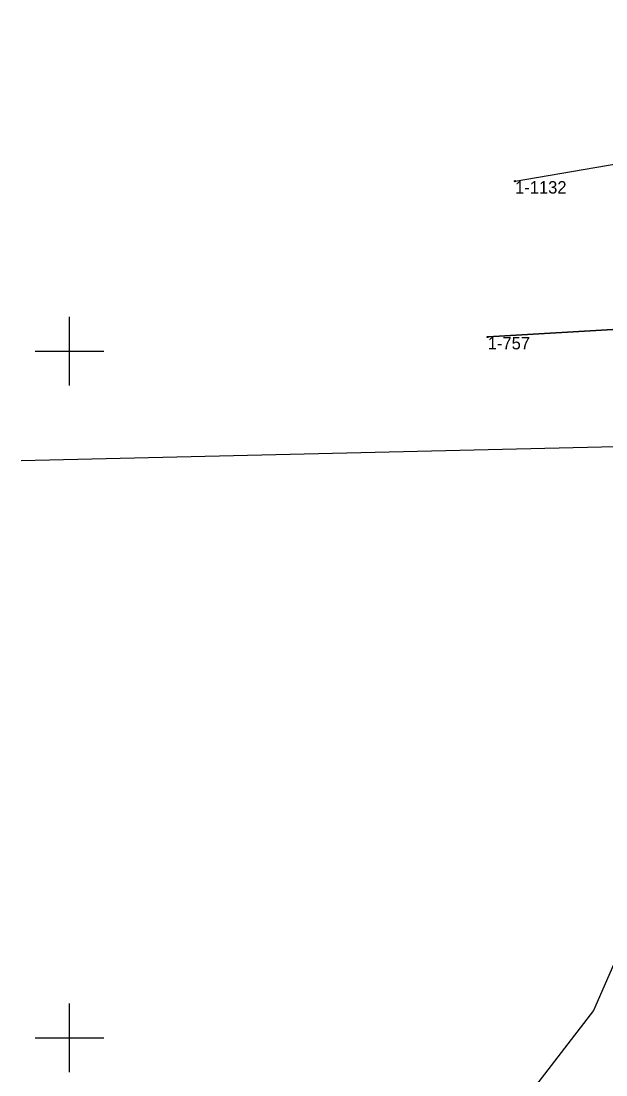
# Model space of a CAD drawing. Extents: x 5598798 to 5599616, y 5661498 to 5662453.
# Drawn here: x 5598996.5 to 5599039.1, y 5661547.3 to 5661624 of the extents above; entities that cross this region are included whole.
import ezdxf

# ---------------------------------------------------------------- set-up
doc = ezdxf.new("R2010")
doc.units = 0
for name, color, linetype in [('Dzialki', 7, 'Continuous'), ('Kontury', 7, 'Continuous'), ('Numery_punktow', 7, 'Continuous'), ('Podzial_sekcyjny_krzyze', 7, 'Continuous'), ('Punkty', 7, 'Continuous'), ('SUPE_L_3', 7, 'Continuous'), ('SUPW_L_0', 7, 'Continuous'), ('Uzytki', 7, 'Continuous')]:
    doc.layers.add(name, color=color, linetype=linetype)

# ---------------------------------------------------------------- blocks, each defined once
blk = doc.blocks.new('GRO')
blk.add_circle((0, 0), 0.045)

msp = doc.modelspace()

# ---------------------------------------------------------------- linework, layer by layer
at = {"layer": 'Dzialki'}
for p, q in [((5599032.45, 5661612.39), (5599100.76, 5661624.05)), ((5599070.32, 5661603.46), (5599030.46, 5661601.04))]:
    msp.add_line(p, q, dxfattribs=at)
at = {"layer": 'Kontury'}
for p, q in [((5599032.45, 5661612.39), (5599100.76, 5661624.05)), ((5599030.46, 5661601.04), (5599070.32, 5661603.46))]:
    msp.add_line(p, q, dxfattribs=at)
at = {"layer": 'Podzial_sekcyjny_krzyze'}
for p, q in [((5599000, 5661597.5), (5599000, 5661602.5)), ((5598997.5, 5661600), (5599002.5, 5661600)), ((5599000, 5661547.5), (5599000, 5661552.5)), ((5598997.5, 5661550), (5599002.5, 5661550))]:
    msp.add_line(p, q, dxfattribs=at)
at = {"layer": 'SUPE_L_3'}
msp.add_line((5598996.482621, 5661592.032784), (5599094.830509, 5661594.368063), dxfattribs=at)
at = {"layer": 'SUPW_L_0'}
for p, q in [((5599041.92742, 5661560.625386), (5599038.151952, 5661551.985555)), ((5599038.151952, 5661551.985555), (5599008.329452, 5661513.189833))]:
    msp.add_line(p, q, dxfattribs=at)
at = {"layer": 'Uzytki'}
for p, q in [((5599032.45, 5661612.39), (5599100.76, 5661624.05)), ((5599070.32, 5661603.46), (5599030.46, 5661601.04))]:
    msp.add_line(p, q, dxfattribs=at)

# ---------------------------------------------------------------- block references
at = {"layer": 'Punkty'}
for p in [(5599032.45, 5661612.39), (5599030.46, 5661601.04)]:
    msp.add_blockref('GRO', p, dxfattribs=at)

# ---------------------------------------------------------------- texts
at = {"layer": 'Numery_punktow'}
for s, p in [('1-1132', (5599032.45, 5661611.49)), ('1-757', (5599030.46, 5661600.14))]:
    msp.add_text(s, height=0.9, dxfattribs=at).set_placement(p)

doc.saveas('drawing.dxf')
